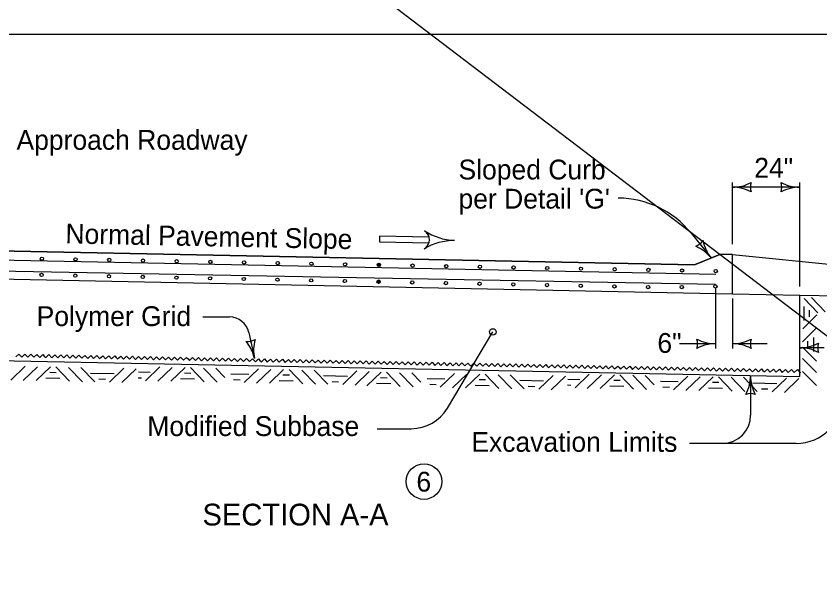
# Model space of a CAD drawing. Extents: x 8925 to 81668, y 4369 to 11918.
# Drawn here: x 17579 to 18391, y 6178 to 6752 of the extents above; entities that cross this region are included whole.
import ezdxf

# ---------------------------------------------------------------- set-up
doc = ezdxf.new("R2010")
doc.units = 0
for name, color, linetype in [('dsnShtPlotShapeBatchPrint', 7, 'Continuous'), ('dsnStdBlock', 7, 'Continuous'), ('dsnStdBorder', 7, 'Continuous'), ('SheetBorder', 7, 'Continuous')]:
    doc.layers.add(name, color=color, linetype=linetype)

msp = doc.modelspace()

# ---------------------------------------------------------------- linework, layer by layer
at = {"layer": 'dsnShtPlotShapeBatchPrint'}
msp.add_line((18285.28, 6480.97), (17553.73, 6494.51), dxfattribs=at)
at = {"layer": 'dsnStdBlock'}
msp.add_lwpolyline([(17303.03, 6733.91), (20438.03, 6733.91), (20438.03, 4723.91), (17303.03, 4723.91)], close=True, dxfattribs=at)
at = {"layer": 'dsnStdBorder'}
for p, q in [((18302.3, 6521.78), (18302.3, 6583.93)), ((18370.36, 6579.2), (18302.3, 6579.2)), ((18370.36, 6478.92), (18370.36, 6583.93)), ((17995.91, 6529), (17995.91, 6529)), ((18260.57, 6532.94), (18280.83, 6507.77)), ((17995.85, 6523.14), (17995.85, 6523.14)), ((18264.02, 6500.8), (17553.77, 6515.06)), ((17553.77, 6515.06), (18264.02, 6500.8)), ((17553.77, 6506.12), (18285.47, 6491.43)), ((18289.54, 6511.38), (18264.02, 6500.8)), ((18264.02, 6500.8), (18289.54, 6511.38)), ((18302.3, 6511.38), (18289.54, 6511.38)), ((18302.3, 6511.38), (18289.54, 6511.38)), ((18302.3, 6471.67), (18302.3, 6511.38)), ((18302.3, 6471.67), (18302.3, 6511.38)), ((18302.3, 6511.38), (18414.58, 6500.15)), ((17553.2, 6486.71), (18302.3, 6471.67)), ((17554.34, 6486.68), (18302.3, 6471.67)), ((18285.29, 6477.19), (18285.29, 6416.45)), ((18302.3, 6471.67), (18370.36, 6470.3)), ((18302.3, 6466.94), (18302.3, 6416.45)), ((18370.36, 6387.88), (18370.36, 6470.3)), ((18370.36, 6470.3), (18548.22, 6466.73)), ((18374.86, 6466.82), (18388.71, 6452.4)), ((18382.08, 6467.76), (18395.93, 6453.33)), ((17767.48, 6448.17), (17794.3, 6448.17)), ((18373.39, 6436.2), (18387.54, 6450.34)), ((17813.83, 6432.47), (17819.64, 6406.1)), ((18014.42, 6356.05), (18060.44, 6433.02)), ((18373.17, 6423.19), (18387.31, 6437.33)), ((17815.25, 6426.02), (17816.37, 6420.92)), ((18285.29, 6421.17), (18248.75, 6421.17)), ((18337.52, 6421.17), (18302.3, 6421.17)), ((18395.08, 6417.05), (18370.36, 6417.05)), ((18373.17, 6417.78), (18387.31, 6403.64)), ((17553.77, 6404.27), (18370.36, 6387.88)), ((17587.99, 6398.33), (17573.56, 6384.47)), ((18373.17, 6406.21), (18387.31, 6392.06)), ((17600.43, 6397.85), (17586.01, 6384)), ((17613.44, 6397.82), (17599.02, 6383.96)), ((17618.85, 6397.71), (17632.71, 6383.28)), ((17631.85, 6397.22), (17645.71, 6382.8)), ((17644.3, 6397.2), (17658.16, 6382.77)), ((17687.52, 6396.33), (17673.1, 6382.47)), ((17699.96, 6395.85), (17685.54, 6382)), ((17724.06, 6397.69), (17709.63, 6383.83)), ((17736.5, 6397.21), (17722.08, 6383.36)), ((17749.51, 6397.18), (17735.09, 6383.32)), ((17754.92, 6397.07), (17768.78, 6382.65)), ((17767.92, 6396.58), (17781.78, 6382.16)), ((17780.37, 6396.56), (17789.47, 6387.08)), ((17823.59, 6395.69), (17809.17, 6381.83)), ((17836.03, 6395.21), (17821.61, 6381.36)), ((17849.04, 6395.18), (17834.62, 6381.32)), ((17854.45, 6395.07), (17868.31, 6380.65)), ((17867.45, 6394.58), (17881.31, 6380.16)), ((17879.9, 6394.56), (17893.76, 6380.14)), ((17923.12, 6393.69), (17908.7, 6379.84)), ((17935.56, 6393.22), (17921.14, 6379.36)), ((17947.61, 6392.46), (17933.19, 6378.6)), ((17953.02, 6392.35), (17966.88, 6377.93)), ((17966.02, 6391.86), (17979.88, 6377.44)), ((17978.48, 6391.84), (17987.58, 6382.37)), ((18021.69, 6390.97), (18007.27, 6377.12)), ((18034.13, 6390.5), (18019.71, 6376.64)), ((18047.14, 6390.46), (18032.72, 6376.61)), ((18052.55, 6390.35), (18066.41, 6375.93)), ((18157.76, 6390.33), (18143.34, 6376.48)), ((18373.17, 6393.14), (18387.31, 6379)), ((18065.56, 6389.87), (18079.41, 6375.44)), ((18078.01, 6389.84), (18091.86, 6375.42)), ((18121.22, 6388.98), (18106.8, 6375.12)), ((18133.67, 6388.5), (18119.24, 6374.64)), ((18170.2, 6389.86), (18155.78, 6376)), ((18183.21, 6389.82), (18168.79, 6375.97)), ((18188.62, 6389.71), (18202.48, 6375.29)), ((18201.62, 6389.23), (18215.48, 6374.8)), ((18214.08, 6389.2), (18223.18, 6379.73)), ((18257.29, 6388.34), (18242.87, 6374.48)), ((18269.74, 6387.86), (18255.31, 6374)), ((18282.74, 6387.83), (18268.32, 6373.97)), ((18288.16, 6387.72), (18302.01, 6373.29)), ((18301.16, 6387.23), (18315.01, 6372.81)), ((18313.61, 6387.21), (18327.46, 6372.78)), ((18320.68, 6388.88), (18320.68, 6348.87)), ((18356.82, 6386.34), (18342.4, 6372.48)), ((18369.27, 6385.86), (18354.84, 6372.01)), ((17943.63, 6335.34), (17977.91, 6335.34)), ((18366.72, 6320.52), (18258.95, 6320.52))]:
    msp.add_line(p, q, dxfattribs=at)
for points in [[(17995.96, 6528.81), (17945.91, 6529.81), (17945.8, 6524.14), (17995.85, 6523.14)], [(17943.73, 6500.68), (17943.99, 6501.23), (17944.3, 6502.09), (17945.18, 6502.22), (17945.95, 6502.07), (17946.65, 6501.49), (17946.54, 6500.66), (17946.38, 6499.8), (17945.68, 6499.41), (17944.94, 6499.36), (17944, 6499.91), (17943.95, 6500.54), (17944.2, 6501.41), (17944.79, 6502.1), (17945.61, 6502.04), (17946.25, 6501.46), (17946.3, 6500.68), (17946.09, 6499.82), (17945.6, 6499.7), (17945.01, 6499.55), (17944.3, 6499.98), (17944.34, 6500.62), (17944.49, 6501.34), (17944.91, 6501.84), (17945.63, 6501.56), (17946.02, 6500.99), (17946.03, 6500.26), (17945.62, 6500.09), (17945.18, 6499.88), (17944.61, 6500.26), (17944.5, 6500.8), (17944.78, 6501.27), (17945.32, 6501.28), (17945.69, 6501.02), (17945.8, 6500.52), (17945.59, 6500.29), (17945.29, 6500.16), (17944.87, 6500.43), (17944.79, 6500.78), (17945.01, 6501.11), (17945.3, 6501.04), (17945.48, 6500.78), (17945.45, 6500.44), (17945.21, 6500.46), (17945.09, 6500.76)], [(17946.42, 6483.68), (17946.17, 6484.24), (17945.9, 6485.1), (17945.02, 6485.27), (17944.24, 6485.15), (17943.53, 6484.6), (17943.6, 6483.77), (17943.72, 6482.9), (17944.42, 6482.48), (17945.15, 6482.4), (17946.11, 6482.92), (17946.19, 6483.55), (17945.97, 6484.43), (17945.41, 6485.14), (17944.58, 6485.12), (17943.92, 6484.56), (17943.85, 6483.78), (17944.02, 6482.91), (17944.5, 6482.78), (17945.09, 6482.6), (17945.81, 6483.01), (17945.79, 6483.64), (17945.68, 6484.37), (17945.27, 6484.89), (17944.55, 6484.63), (17944.13, 6484.08), (17944.1, 6483.35), (17944.49, 6483.17), (17944.94, 6482.93), (17945.51, 6483.29), (17945.64, 6483.83), (17945.39, 6484.31), (17944.85, 6484.35), (17944.47, 6484.09), (17944.33, 6483.6), (17944.54, 6483.36), (17944.83, 6483.23), (17945.26, 6483.48), (17945.35, 6483.82), (17945.15, 6484.16), (17944.86, 6484.1), (17944.67, 6483.85), (17944.68, 6483.51), (17944.92, 6483.52), (17945.06, 6483.82)], [(18374.97, 6444.64), (18374.97, 6458.83)], [(18380.06, 6448.47), (18380.06, 6455)], [(18378.67, 6417.22), (18378.67, 6423.75)], [(18384.52, 6413.39), (18384.52, 6427.58)], [(17578.5, 6407.79), (17581.58, 6410.75), (17584.55, 6407.67), (17587.63, 6410.63), (17590.6, 6407.55), (17593.68, 6410.51), (17596.65, 6407.42), (17599.73, 6410.39), (17602.69, 6407.3), (17605.78, 6410.27), (17607.26, 6408.72)], [(17607.26, 6408.72), (17608.74, 6407.18), (17611.83, 6410.14), (17614.79, 6407.06), (17617.88, 6410.02), (17620.84, 6406.94), (17623.93, 6409.9), (17626.89, 6406.82), (17629.97, 6409.78), (17632.94, 6406.7), (17636.02, 6409.66), (17638.99, 6406.57), (17642.07, 6409.54), (17645.04, 6406.45), (17648.12, 6409.42), (17651.09, 6406.33), (17654.17, 6409.3), (17657.13, 6406.21), (17660.22, 6409.17), (17663.18, 6406.09), (17666.27, 6409.05), (17669.23, 6405.97), (17672.32, 6408.93), (17675.28, 6405.85), (17678.37, 6408.81), (17679.85, 6407.27)], [(17679.85, 6407.27), (17681.33, 6405.73), (17684.41, 6408.69), (17687.38, 6405.6), (17690.46, 6408.56), (17693.43, 6405.48), (17696.51, 6408.45), (17699.48, 6405.36), (17702.56, 6408.33), (17705.52, 6405.24), (17708.61, 6408.2), (17711.57, 6405.12), (17714.66, 6408.08), (17717.62, 6404.99), (17720.71, 6407.96), (17723.67, 6404.87), (17726.76, 6407.84), (17729.72, 6404.76), (17732.8, 6407.72), (17735.77, 6404.63), (17738.85, 6407.59), (17741.82, 6404.51), (17744.9, 6407.47), (17747.87, 6404.39), (17750.95, 6407.35), (17752.43, 6405.81)], [(17752.43, 6405.81), (17753.91, 6404.27), (17757, 6407.23), (17759.96, 6404.15), (17763.05, 6407.11), (17766.01, 6404.02), (17769.1, 6406.99), (17772.06, 6403.9), (17775.15, 6406.87), (17778.11, 6403.78), (17781.19, 6406.75), (17784.16, 6403.66), (17787.24, 6406.62), (17790.21, 6403.54), (17793.29, 6406.5), (17796.25, 6403.42), (17799.34, 6406.38), (17802.3, 6403.3), (17805.39, 6406.26), (17808.35, 6403.17), (17811.44, 6406.14), (17814.4, 6403.05), (17817.49, 6406.02), (17820.45, 6402.93), (17823.54, 6405.9), (17825.02, 6404.35)], [(17825.02, 6404.35), (17826.5, 6402.81), (17829.58, 6405.77), (17832.55, 6402.69), (17835.63, 6405.65), (17838.6, 6402.57), (17841.68, 6405.53), (17844.65, 6402.45), (17847.73, 6405.41), (17850.69, 6402.33), (17853.78, 6405.29), (17856.74, 6402.2), (17859.83, 6405.17), (17862.79, 6402.08), (17865.88, 6405.05), (17868.84, 6401.96), (17871.93, 6404.93), (17874.89, 6401.84), (17877.97, 6404.8), (17880.94, 6401.72), (17884.02, 6404.68), (17886.99, 6401.6), (17890.07, 6404.56), (17893.04, 6401.48), (17896.12, 6404.44), (17897.6, 6402.89)], [(17897.6, 6402.89), (17899.08, 6401.36), (17902.17, 6404.32), (17905.13, 6401.23), (17908.22, 6404.19), (17911.18, 6401.11), (17914.27, 6404.08), (17917.23, 6400.99), (17920.32, 6403.96), (17923.28, 6400.87), (17926.36, 6403.83), (17929.33, 6400.75), (17932.41, 6403.71), (17935.38, 6400.62), (17938.46, 6403.59), (17941.43, 6400.5), (17944.51, 6403.47), (17947.47, 6400.38), (17950.56, 6403.35), (17953.52, 6400.26), (17956.61, 6403.22), (17959.57, 6400.14), (17962.66, 6403.1), (17965.62, 6400.02), (17968.71, 6402.98), (17970.19, 6401.44)], [(17970.19, 6401.44), (17971.67, 6399.9), (17974.75, 6402.86), (17977.72, 6399.78), (17980.8, 6402.74), (17983.77, 6399.65), (17986.85, 6402.62), (17989.82, 6399.53), (17992.9, 6402.5), (17995.86, 6399.41), (17998.95, 6402.38), (18001.91, 6399.29), (18005, 6402.25), (18007.96, 6399.17), (18011.05, 6402.13), (18014.01, 6399.05), (18017.1, 6402.01), (18020.06, 6398.93), (18023.14, 6401.89), (18026.11, 6398.81), (18029.19, 6401.77), (18032.16, 6398.68), (18035.24, 6401.65), (18038.21, 6398.56), (18041.29, 6401.53), (18042.77, 6399.98)], [(18042.77, 6399.98), (18044.25, 6398.44), (18047.34, 6401.4), (18050.3, 6398.32), (18053.38, 6401.28), (18056.35, 6398.2), (18059.44, 6401.16), (18062.4, 6398.08), (18065.49, 6401.04), (18068.45, 6397.96), (18071.53, 6400.92), (18074.49, 6397.83), (18077.58, 6400.8), (18080.54, 6397.71), (18083.63, 6400.68), (18086.6, 6397.59), (18089.68, 6400.56), (18092.65, 6397.47), (18095.73, 6400.43), (18098.69, 6397.35), (18101.78, 6400.31), (18104.74, 6397.23), (18107.83, 6400.19), (18110.79, 6397.11), (18113.88, 6400.07), (18115.35, 6398.53)], [(18115.35, 6398.53), (18116.84, 6396.99), (18119.93, 6399.95), (18122.89, 6396.86), (18125.97, 6399.83), (18128.93, 6396.74), (18132.02, 6399.71), (18134.99, 6396.62), (18138.07, 6399.59), (18141.04, 6396.5), (18144.12, 6399.46), (18147.08, 6396.38), (18150.17, 6399.34), (18153.13, 6396.25), (18156.21, 6399.22), (18159.18, 6396.14), (18162.27, 6399.1), (18165.23, 6396.02), (18168.32, 6398.98), (18171.28, 6395.89), (18174.36, 6398.85), (18177.32, 6395.77), (18180.41, 6398.73), (18183.37, 6395.65), (18186.46, 6398.61), (18187.94, 6397.07)], [(18187.94, 6397.07), (18189.42, 6395.53), (18192.51, 6398.49), (18195.47, 6395.41), (18198.56, 6398.37), (18201.52, 6395.28), (18204.6, 6398.25), (18207.57, 6395.16), (18210.65, 6398.13), (18213.62, 6395.04), (18216.71, 6398.01), (18219.67, 6394.92), (18222.75, 6397.88), (18225.71, 6394.8), (18228.8, 6397.76), (18231.76, 6394.68), (18234.85, 6397.64), (18237.81, 6394.56), (18240.9, 6397.52), (18243.86, 6394.43), (18246.95, 6397.4), (18249.91, 6394.31), (18252.99, 6397.28), (18255.96, 6394.19), (18259.04, 6397.16), (18260.53, 6395.61)], [(17612.77, 6392.33), (17619.3, 6392.2)], [(17653.77, 6391.53), (17677.83, 6391.05)], [(17702.34, 6392.65), (17714.37, 6392.41)], [(17748.84, 6391.69), (17755.37, 6391.56)], [(17795.84, 6390.77), (17813.9, 6390.41)], [(18260.53, 6395.61), (18262.01, 6394.07), (18265.1, 6397.04), (18268.06, 6393.95), (18271.14, 6396.91), (18274.1, 6393.83), (18277.19, 6396.79), (18280.15, 6393.71), (18283.24, 6396.67), (18286.2, 6393.59), (18289.29, 6396.55), (18292.25, 6393.46), (18295.34, 6396.43), (18298.3, 6393.34), (18301.38, 6396.31), (18304.35, 6393.22), (18307.43, 6396.19), (18310.4, 6393.1), (18313.48, 6396.06), (18316.45, 6392.98), (18319.53, 6395.94), (18322.5, 6392.86), (18325.58, 6395.82), (18328.54, 6392.74), (18331.63, 6395.7), (18333.11, 6394.16)], [(18333.11, 6394.16), (18334.59, 6392.62), (18337.68, 6395.58), (18340.64, 6392.49), (18343.73, 6395.45), (18346.69, 6392.37), (18349.78, 6395.34), (18352.74, 6392.25), (18355.82, 6395.22), (18358.79, 6392.13), (18361.87, 6395.09), (18364.84, 6392.01), (18367.92, 6394.97), (18370.89, 6391.88), (18371.1, 6392.07)], [(17608.82, 6386.55), (17623.01, 6386.27)], [(17662.42, 6385.56), (17668.95, 6385.43)], [(17702.22, 6386.85), (17705.49, 6386.78)], [(17744.89, 6385.91), (17759.08, 6385.63)], [(17798.49, 6384.92), (17805.02, 6384.79)], [(17844.42, 6383.92), (17858.61, 6383.63)], [(17848.37, 6389.69), (17854.9, 6389.56)], [(17889.38, 6388.89), (17913.43, 6388.41)], [(17898.02, 6382.92), (17904.55, 6382.79)], [(17946.94, 6386.97), (17953.47, 6386.84)], [(17993.94, 6386.05), (18012, 6385.69)], [(18046.47, 6384.98), (18053.01, 6384.85)], [(18087.48, 6384.18), (18111.53, 6383.69)], [(18136.04, 6385.29), (18148.07, 6385.05)], [(18182.54, 6384.34), (18189.07, 6384.21)], [(18229.54, 6383.42), (18247.6, 6383.05)], [(18282.08, 6382.34), (18288.61, 6382.21)], [(17942.99, 6381.2), (17957.18, 6380.91)], [(17996.59, 6380.2), (18003.12, 6380.07)], [(18042.53, 6379.2), (18056.72, 6378.91)], [(18096.12, 6378.2), (18102.65, 6378.07)], [(18135.92, 6379.5), (18139.19, 6379.43)], [(18178.6, 6378.56), (18192.78, 6378.27)], [(18232.19, 6377.56), (18238.72, 6377.43)], [(18278.13, 6376.56), (18292.32, 6376.28)], [(18323.08, 6381.54), (18347.13, 6381.06)], [(18331.72, 6375.57), (18338.26, 6375.43)]]:
    msp.add_lwpolyline(points, dxfattribs=at)
for centre, radius in [((17604.85, 6507.01), 1.65), ((17638.88, 6506.38), 1.65), ((17672.91, 6505.76), 1.65), ((17706.95, 6505.13), 1.65), ((17740.98, 6504.51), 1.65), ((17775.02, 6503.88), 1.65), ((17809.05, 6503.25), 1.65), ((17843.08, 6502.63), 1.65), ((17877.12, 6502), 1.65), ((17911.15, 6501.37), 1.65), ((17945.18, 6500.75), 1.65), ((17945.25, 6500.75), 1.65), ((17979.22, 6500.12), 1.65), ((18013.25, 6499.49), 1.65), ((18047.29, 6498.87), 1.65), ((18081.32, 6498.24), 1.65), ((18115.35, 6497.62), 1.65), ((18149.39, 6496.99), 1.65), ((18183.42, 6496.36), 1.65), ((18217.45, 6495.74), 1.65), ((18251.49, 6495.11), 1.65), ((18285.52, 6494.48), 1.65), ((17604.57, 6490.64), 1.65), ((17638.6, 6489.95), 1.65), ((17672.64, 6489.27), 1.65), ((17706.67, 6488.59), 1.65), ((17740.7, 6487.9), 1.65), ((17774.74, 6487.22), 1.65), ((17808.77, 6486.54), 1.65), ((17842.8, 6485.85), 1.65), ((17876.83, 6485.17), 1.65), ((17910.87, 6484.49), 1.65), ((17944.9, 6483.8), 1.65), ((17944.9, 6483.8), 1.65), ((17978.93, 6483.12), 1.65), ((18012.96, 6482.44), 1.65), ((18047, 6481.76), 1.65), ((18081.03, 6481.07), 1.65), ((18115.06, 6480.39), 1.65), ((18149.1, 6479.7), 1.65), ((18183.13, 6479.02), 1.65), ((18217.16, 6478.34), 1.65), ((18251.18, 6478.34), 1.65), ((18285.22, 6479.02), 1.65), ((18060.44, 6433.02), 3.31), ((17990.84, 6281.91), 18)]:
    msp.add_circle(centre, radius, dxfattribs=at)
for centre, radius, start, end in [((18302.3, 6619.38), 40.18, 270, 298.07249), ((18302.3, 6619.38), 40.18, 270, 298.07249), ((18302.3, 6539.03), 40.18, 61.92751, 90), ((18302.3, 6539.03), 40.18, 61.92751, 90), ((18335.99, 6579.2), 15.52, 162.26665, 197.73335), ((18335.99, 6579.2), 15.52, 162.26665, 197.73335), ((18336.68, 6579.2), 15.52, 342.26665, 17.73335), ((18370.36, 6619.38), 40.18, 241.92751, 270), ((18336.68, 6579.2), 15.52, 342.26665, 17.73335), ((18370.36, 6619.38), 40.18, 241.92751, 270), ((18370.36, 6539.03), 40.18, 90, 118.07249), ((18370.36, 6539.03), 40.18, 90, 118.07249), ((18186.94, 6473.66), 94.53, 38.83776, 90), ((17985.62, 6526.18), 10.67, 300.56474, 57.13538), ((18024.49, 6586.34), 60.95, 237.1358, 267.16583), ((18024.49, 6586.34), 60.95, 237.13628, 267.16583), ((17985.62, 6526.18), 10.67, 14.25957, 57.13266), ((18022.04, 6464.51), 60.95, 90.53429, 120.56432), ((18022.04, 6464.51), 60.95, 90.53429, 120.56385), ((17985.62, 6526.18), 10.67, 300.56746, 343.42998), ((18259.71, 6534.01), 15.52, 291.10478, 326.57148), ((18312.13, 6532.97), 40.18, 190.76564, 218.83813), ((18249.54, 6482.58), 40.18, 38.83813, 66.91062), ((17794.3, 6428.17), 20, 12.43142, 90), ((17812.4, 6439), 15.52, 264.68499, 300.15169), ((17780.41, 6397.46), 40.18, 12.41834, 40.49083), ((17858.88, 6414.74), 40.18, 164.34585, 192.41834), ((18251.6, 6421.18), 15.52, 342.26665, 17.73335), ((18285.29, 6461.35), 40.18, 241.92751, 270), ((18302.3, 6461.35), 40.18, 270, 298.07249), ((18335.99, 6421.18), 15.52, 162.26665, 197.73335), ((18285.29, 6381), 40.18, 90, 118.07249), ((18302.3, 6381), 40.18, 61.92751, 90), ((18370.36, 6457.22), 40.18, 270, 298.07249), ((18370.36, 6376.87), 40.18, 61.92751, 90), ((18404.05, 6417.05), 15.52, 162.26665, 197.73335), ((18280.5, 6388.88), 40.18, 331.92751, 360), ((18360.85, 6388.88), 40.18, 180, 208.07249), ((18320.68, 6355.19), 15.52, 72.26665, 107.73335), ((18366.72, 6367.78), 47.27, 270, 360), ((17977.91, 6377.88), 42.54, 270, 329.12488), ((18292.32, 6348.88), 28.36, 270, 360)]:
    msp.add_arc(centre, radius, start, end, dxfattribs=at)
at = {"layer": 'SheetBorder'}
msp.add_line((17092.54, 7422.93), (21027.23, 4427.13), dxfattribs=at)

# ---------------------------------------------------------------- texts
at = {"layer": 'dsnShtPlotShapeBatchPrint'}
for s, height, p in [('Approach Roadway', 20, (17579.17, 6617.05)), ('Sloped Curb', 20, (18025.66, 6587.1)), ('24"', 20, (18324.42, 6588.85)), ("per Detail 'G'", 20, (18025.66, 6557.64)), ('Polymer Grid', 20, (17599.54, 6438.98)), ('6"', 20, (18226.57, 6411.92)), ('Modified Subbase', 20, (17711.31, 6327.93)), ('Excavation Limits', 20, (18038.64, 6311.98)), ('6', 20, (17983.16, 6271.8)), ('SECTION A-A', 22, (17767.04, 6237.54))]:
    msp.add_text(s, height=height, dxfattribs=at).set_placement(p)
msp.add_text('Normal Pavement Slope', height=20, rotation=358.85018, dxfattribs=at).set_placement((17628.47, 6522.49))

doc.saveas('drawing.dxf')
